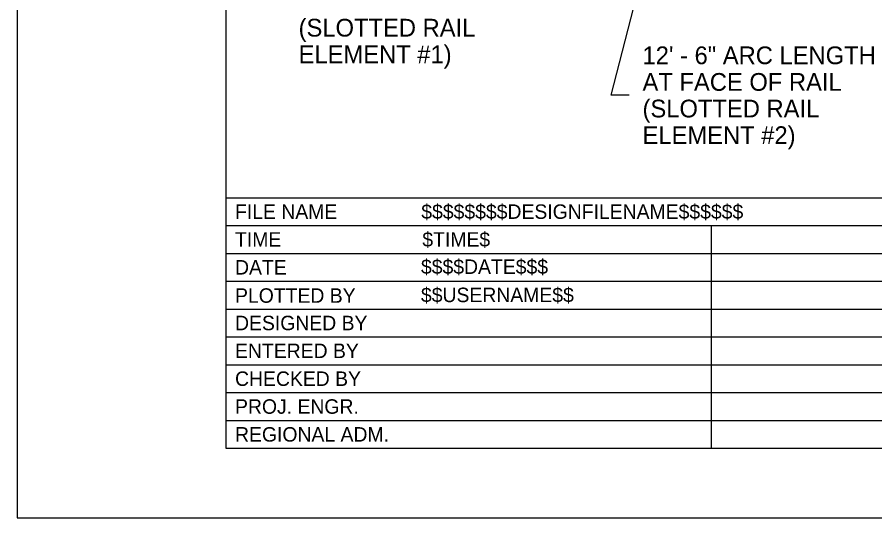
# Model space of a CAD drawing. Extents: x 1312564.2 to 1312581.5, y 1207298.4 to 1207352.6.
# Drawn here: x 1312564.478 to 1312568.33, y 1207298.421 to 1207300.671 of the extents above; entities that cross this region are included whole.
import ezdxf

# ---------------------------------------------------------------- set-up
doc = ezdxf.new("R2010")
doc.units = 0
for name, color, linetype in [('Level 1', 7, 'Continuous'), ('Level 15', 7, 'Continuous'), ('Level 2', 7, 'Continuous'), ('Level 20', 7, 'Continuous'), ('Level 36', 7, 'Continuous'), ('SH_GI_SheetTextInCells', 7, 'Continuous')]:
    doc.layers.add(name, color=color, linetype=linetype)

msp = doc.modelspace()

# ---------------------------------------------------------------- linework, layer by layer
at = {"layer": 'Level 1'}
for p, q in [((1312565.4155, 1207309.1084), (1312565.4155, 1207298.7334)), ((1312565.4155, 1207299.8593), (1312581.1655, 1207299.8593)), ((1312565.4155, 1207299.7342), (1312572.8721, 1207299.7342)), ((1312567.5945, 1207299.7342), (1312567.5945, 1207298.7334)), ((1312565.4155, 1207299.6091), (1312567.5976, 1207299.6091)), ((1312567.5976, 1207299.6091), (1312570.8621, 1207299.6091)), ((1312565.4155, 1207299.484), (1312567.5976, 1207299.484)), ((1312567.5976, 1207299.484), (1312570.8621, 1207299.484)), ((1312565.4155, 1207299.3589), (1312570.8621, 1207299.3589)), ((1312565.4155, 1207299.2338), (1312570.8621, 1207299.2338)), ((1312565.4155, 1207299.1087), (1312570.8621, 1207299.1087)), ((1312565.4155, 1207298.9836), (1312570.8621, 1207298.9836)), ((1312565.4155, 1207298.8585), (1312570.8621, 1207298.8585)), ((1312565.4155, 1207298.7334), (1312581.1655, 1207298.7334))]:
    msp.add_line(p, q, dxfattribs=at)
at = {"layer": 'Level 15'}
for points in [[(1312567.1452, 1207300.3197), (1312567.3226, 1207301.0077)], [(1312567.2266, 1207300.3197), (1312567.1452, 1207300.3197)]]:
    msp.add_lwpolyline(points, dxfattribs=at)
at = {"layer": 'Level 2'}
msp.add_lwpolyline([(1312564.478, 1207298.4209), (1312581.478, 1207298.4209), (1312581.478, 1207309.4209), (1312564.478, 1207309.4209)], close=True, dxfattribs=at)

# ---------------------------------------------------------------- texts
at = {"layer": 'Level 20'}
for s, p in [('(SLOTTED RAIL', (1312565.7419, 1207300.5833)), ('ELEMENT #1)', (1312565.7419, 1207300.4637)), ('12\' - 6" ARC LENGTH', (1312567.2864, 1207300.4592)), ('AT FACE OF RAIL', (1312567.2864, 1207300.3396)), ('(SLOTTED RAIL', (1312567.2864, 1207300.22)), ('ELEMENT #2)', (1312567.2864, 1207300.1004))]:
    msp.add_text(s, height=0.079729, dxfattribs=at).set_placement(p)
at = {"layer": 'Level 36'}
for s, height, p in [('$$$$$$$$DESIGNFILENAME$$$$$$', 0.065052, (1312566.2929, 1207299.7643)), ('$TIME$', 0.06505, (1312566.2975, 1207299.6393)), ('$$$$DATE$$$', 0.065052, (1312566.2914, 1207299.5169)), ('$$USERNAME$$', 0.065052, (1312566.2914, 1207299.3901))]:
    msp.add_text(s, height=height, dxfattribs=at).set_placement(p)
at = {"layer": 'SH_GI_SheetTextInCells'}
for s, height, p in [('FILE NAME', 0.06505, (1312565.4565, 1207299.7643)), ('TIME', 0.06505, (1312565.4565, 1207299.6392)), ('DATE', 0.06505, (1312565.4565, 1207299.5141)), ('PLOTTED BY', 0.06505, (1312565.4565, 1207299.3872)), ('DESIGNED BY', 0.065052, (1312565.4565, 1207299.2639)), ('ENTERED BY', 0.06505, (1312565.4565, 1207299.1388)), ('CHECKED BY', 0.06505, (1312565.4565, 1207299.0137)), ('PROJ. ENGR.', 0.065052, (1312565.4565, 1207298.8886)), ('REGIONAL ADM.', 0.065052, (1312565.4565, 1207298.7635))]:
    msp.add_text(s, height=height, dxfattribs=at).set_placement(p)

doc.saveas('drawing.dxf')
